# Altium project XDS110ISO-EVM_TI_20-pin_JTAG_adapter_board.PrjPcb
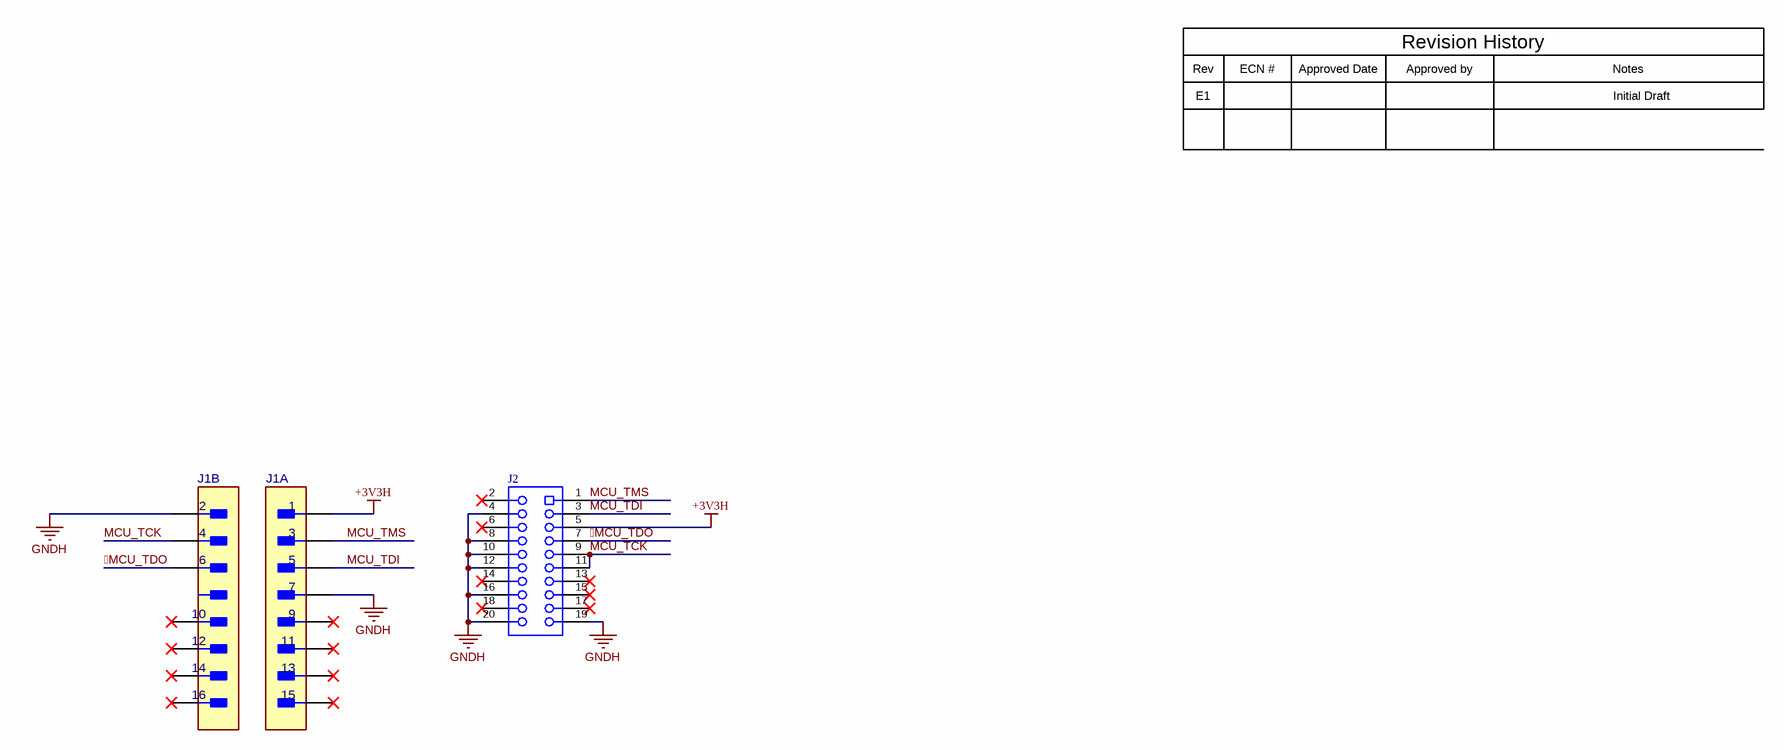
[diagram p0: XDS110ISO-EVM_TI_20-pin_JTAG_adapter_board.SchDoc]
TID: N/A; TechSupport: http://www.ti.com/support; SCH_Rev: A; PRJ_Number: XDS110ISO-EVM_TI_20-pin_JTAG_adapter_board; PRJ_Engineer: Sumit Patil; PRJ_Customer: XDS110ISO-EVM; PCB_Rev: A; PCB_Layout: Sumit Patil; Orderable: XDS110ISO-EVM_TI_20-pin_JTAG_adapter_board; DrawnBy: Sumit Patil; CopyrightYear: 2022
1 sheet, 2 parts. Net scope: global (net labels, ports and power ports of the same name join across sheets).
Board file: XDS110ISO-EVM_TI_20-pin_JTAG_adapter_board.PcbDoc

## Sheet XDS110ISO-EVM_TI_20-pin_JTAG_adapter_board.SchDoc
size 431 x 279 mm; Date: Not shown in title block; ApprovedBy: Not shown in title block; CheckedBy: Not shown in title block; Author: Not shown in title block; CompanyName: Not shown in title block; DrawnBy: Cody Watkins; Engineer: Not shown in title block; Organization: Not shown in title block; Address1: Not shown in title block; Address2: Not shown in title block; Address3: Not shown in title block; Address4: Not shown in title block; DocumentNumber: 1; Revision: Use project parameter SCH_Rev; SheetNumber: 1; SheetTotal: 8; PageSetup: Record=PageOptions¦CenterHorizontal=True¦CenterVertical=True¦PrintScale=1.00¦XCorrection=1.00¦YCorrection=1.00¦PrintKind=0¦BorderSize=5000000¦LeftOffset=0¦BottomOffset=0¦Orientation=2¦PaperLength=1000¦PaperWidth=1000¦Scale=100¦PaperSource=15¦PrintQuality=600¦MediaType=1¦DitherType=10¦PaperKind=Letter¦PrintScaleMode=1

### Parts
J1  TSM-108-01-L-DV-008-P-TR  [FP-TSM-108-01-L-DV-008-P-TR_HDR15-MFG]  (value not drawn)  (parts A,B of 2)
J2  RSM-110-02-L-D  [Samtec_RSM-110-02-x-D]  (value not drawn)

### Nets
+3V3H: J1.1 J2.5
GNDH: J1.2 J1.7 J2.4 J2.8 J2.10 J2.12 J2.16 J2.19 J2.20
MCU_TDO: J1.6 J2.7
MCU_TCK: J1.4 J2.9 J2.11
MCU_TDI: J1.5 J2.3
MCU_TMS: J1.3 J2.1

Not connected (* = marked no-connect by the designer): J1 9* 10* 11* 12* 13* 14* 15* 16*; J2 2* 6* 13* 14* 15* 17* 18*

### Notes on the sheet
- Rev
- E1
- ECN #
- Approved Date
- Approved by
- Revision History
- Notes
- Initial Draft

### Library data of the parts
J1 = CMP-0121706-1: Conn Unshrouded HDR 16 POS 2.54mm Solder ST SMT; Manufacturer: Samtec; ContactFinish: Gold,Nickel; Row_Count: 2; AEC Qualified: No; Conn Gender: Male; Conn Orientation: Vertical; SizeZ_mm: 10.16mm; Standoff Height: 1.02mm
J2 = CMP-0081743-1: Receptacle, 1.27mm, 10x2, Gold with Tin tail, SMT; Manufacturer: Samtec; Pitch_mm: 1.27; Gender: Female; Cert_UL: Y; Current_A: 3.1A; RowSpacing_mm: 2.54; Row_Count: 2; CompType: Socket Strip

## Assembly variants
001: not fitted FID1 FID2 FID3 FID4 FID5 FID6 R17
